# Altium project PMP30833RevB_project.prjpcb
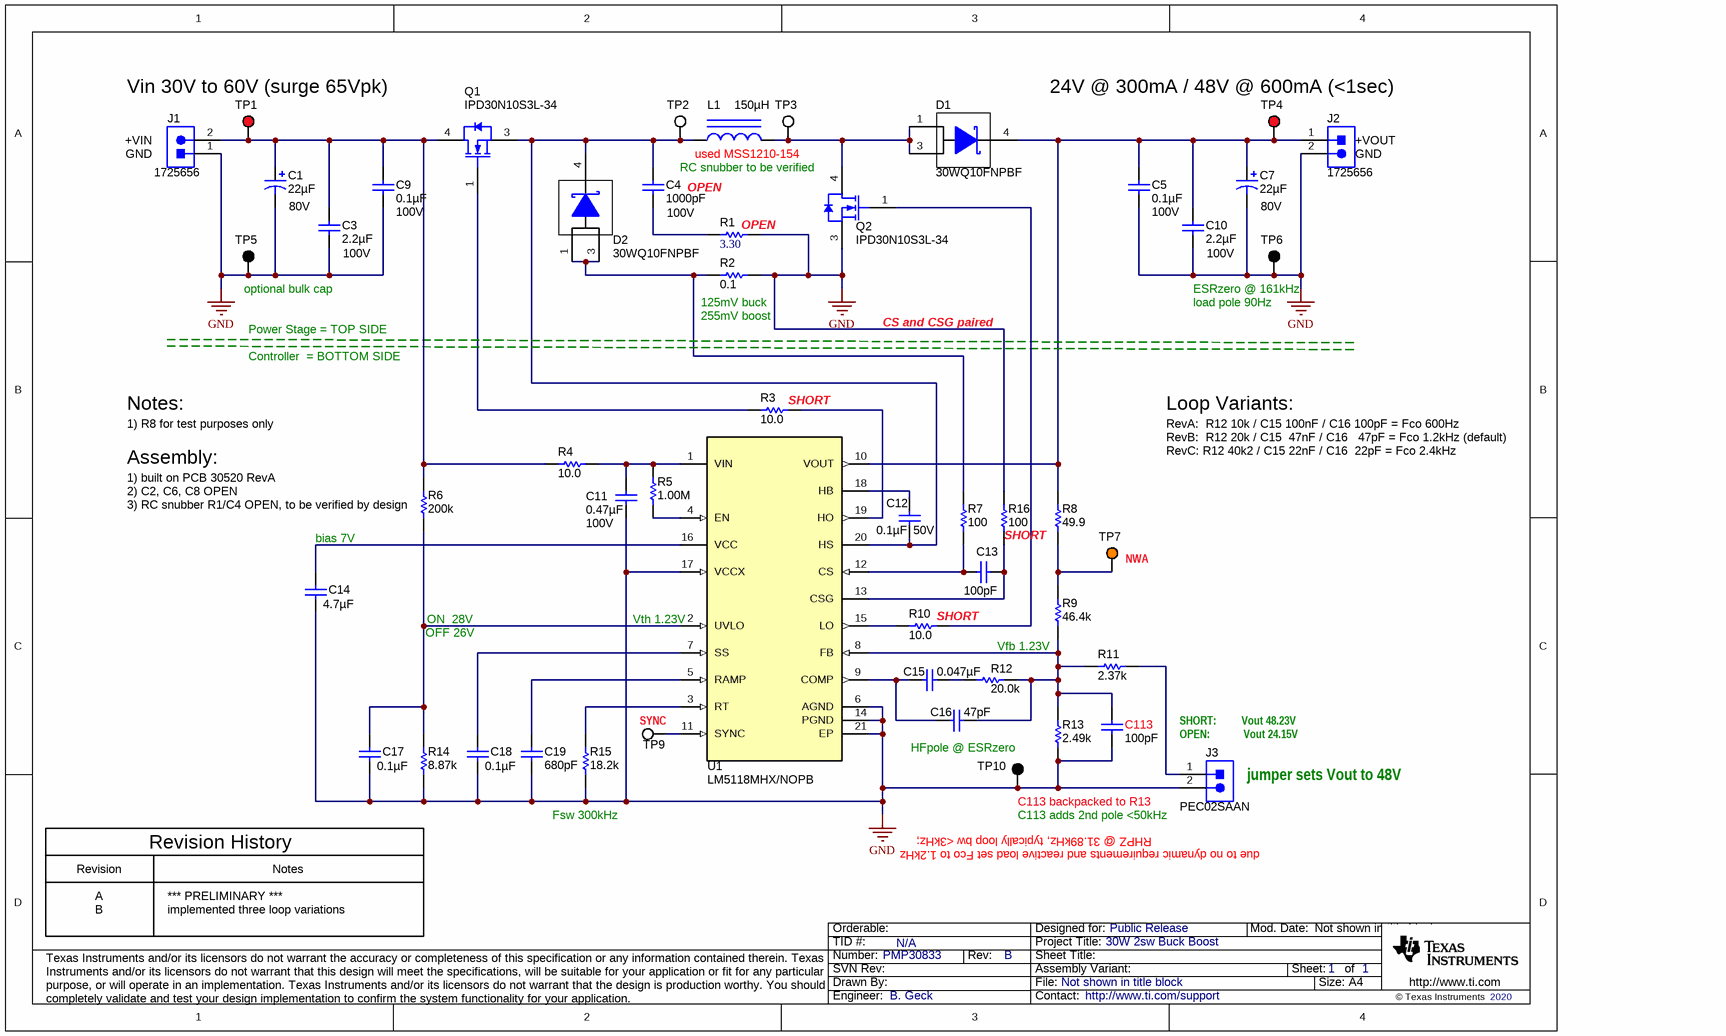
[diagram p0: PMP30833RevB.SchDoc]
CopyrightYear: 2020; PCB_Layout: B. Geck; PCB_Rev: A; PRJ_Customer: Public Release; PRJ_Engineer: B. Geck; PRJ_Number: PMP30833; PRJ_Title: 30W 2sw Buck Boost; SCH_Rev: B; TechSupport: http://www.ti.com/support; TID: N/A
1 sheet, 51 parts. Net scope: global (net labels, ports and power ports of the same name join across sheets).
Board file: PMP30520RevA_board.PcbDoc

## Sheet PMP30833RevB.SchDoc
size A4; Date: Not shown in title block; ApprovedBy: Not shown in title block; CheckedBy: Not shown in title block; Author: Not shown in title block; CompanyName: Not shown in title block; Engineer: Not shown in title block; Organization: Not shown in title block; Address1: Not shown in title block; Address2: Not shown in title block; Address3: Not shown in title block; Address4: Not shown in title block; DocumentNumber: 1; Revision: Use project parameter SCH_Rev; SheetNumber: 1; SheetTotal: 1; PageSetup: Record=PageOptions¦CenterHorizontal=True¦CenterVertical=True¦PrintScale=0.94¦XCorrection=1.00¦YCorrection=1.00¦PrintKind=0¦BorderSize=5000000¦LeftOffset=0¦BottomOffset=0¦Orientation=2¦PaperLength=1000¦PaperWidth=1000¦Scale=100¦PaperSource=15¦PrintQuality=600¦MediaType=1¦DitherType=10¦PrintScaleMode=1¦PaperKind=Letter

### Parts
C1  ValueDisplayed: 22µF  Value2: 80V  [SM_RADIAL_8MM]  (hidden comment: EEHZC1K220P)
C3  ValueDisplayed: 2.2µF  Value2: 100V  [1210_270]  (hidden comment: GRM32ER72A225KA35L)
C4  ValueDisplayed: 1000pF  Value2: 100V  [0603]  (hidden comment: GRM188R72A102KA01D)
C5  ValueDisplayed: 0.1µF  Value2: 100V  [0603]  (hidden comment: GRM188R72A104KA35D)
C7  ValueDisplayed: 22µF  Value2: 80V  [SM_RADIAL_8MM]  (hidden comment: EEHZC1K220P)
C9  ValueDisplayed: 0.1µF  Value2: 100V  [0603]  (hidden comment: GRM188R72A104KA35D)
C10  ValueDisplayed: 2.2µF  Value2: 100V  [1210_270]  (hidden comment: GRM32ER72A225KA35L)
C11  ValueDisplayed: 0.47µF  Value2: 100V  [0805_HV]  (hidden comment: GRM21BR72A474KA73L)
C12  ValueDisplayed: 0.1µF  Value2: 50V  [0603]  (hidden comment: GCM188R71H104KA57D)
C13  ValueDisplayed: 100pF  [0603]  (hidden comment: GRM1885C1H101JA01D)
C14  ValueDisplayed: 4.7µF  [0603]  (hidden comment: GRM188Z71C475KE21D)
C15  ValueDisplayed: 0.047µF  [0603]  (hidden comment: GRM188R71E473KA01D)
C16  ValueDisplayed: 47pF  [0603]  (hidden comment: GRM1885C1H470JA01D)
C17  ValueDisplayed: 0.1µF  [0603]  (hidden comment: GRM188R71E104KA01D)
C18  ValueDisplayed: 0.1µF  [0603]  (hidden comment: GRM188R71E104KA01D)
C19  ValueDisplayed: 680pF  [0603]  (hidden comment: GRM1885C1E681JA01D)
C113  ValueDisplayed: 100pF  [0603]  (hidden comment: GRM1885C1H101JA01D)
D1  30WQ10FNPBF  [DPAK]
D2  30WQ10FNPBF  [DPAK]
J1  1725656  [CONN_1725656]
J2  1725656  [CONN_1725656]
J3  PEC02SAAN  [CONN_PEC02SAAN]
L1  ValueDisplayed: 150µH  [MSS1210]  (hidden comment: MSS1210-154KE)
Q1  IPD30N10S3L-34  [DPAK]
Q2  IPD30N10S3L-34  [DPAK]
R1  ValueDisplayed: 3.30  [1210M]  (hidden comment: CRCW12103R30FKEAHP)
R2  ValueDisplayed: 0.1  [1206]  (hidden comment: ERJ-8BWFR100V)
R3  ValueDisplayed: 10.0  [0603]  (hidden comment: CRCW060310R0FKEA)
R4  ValueDisplayed: 10.0  [0603]  (hidden comment: CRCW060310R0FKEA)
R5  ValueDisplayed: 1.00M  [0603]  (hidden comment: CRCW06031M00FKEA)
R6  ValueDisplayed: 200k  [0603]  (hidden comment: CRCW0603200KFKEA)
R7  ValueDisplayed: 100  [0603]  (hidden comment: CRCW0603100RFKEA)
R8  ValueDisplayed: 49.9  [0603]  (hidden comment: CRCW060349R9FKEA)
R9  ValueDisplayed: 46.4k  [0603]  (hidden comment: CRCW060346K4FKEA)
R10  ValueDisplayed: 10.0  [0603]  (hidden comment: CRCW060310R0FKEA)
R11  ValueDisplayed: 2.37k  [0603]  (hidden comment: CRCW06032K37FKEA)
R12  ValueDisplayed: 20.0k  [0603]  (hidden comment: CRCW060320K0FKEA)
R13  ValueDisplayed: 2.49k  [0603]  (hidden comment: CRCW06032K49FKEA)
R14  ValueDisplayed: 8.87k  [0603]  (hidden comment: CRCW06038K87FKEA)
R15  ValueDisplayed: 18.2k  [0603]  (hidden comment: CRCW060318K2FKEA)
R16  ValueDisplayed: 100  [0603]  (hidden comment: CRCW0603100RFKEA)
TP1  5000  [Keystone5000]  (value not drawn)
TP2  5002  [Keystone5002]  (value not drawn)
TP3  5002  [Keystone5002]  (value not drawn)
TP4  5000  [Keystone5000]  (value not drawn)
TP5  5001  [Keystone5001]  (value not drawn)
TP6  5001  [Keystone5001]  (value not drawn)
TP7  5003  [Keystone5003]  (value not drawn)
TP9  5002  [Keystone5002]  (value not drawn)
TP10  5001  [Keystone5001]  (value not drawn)
U1  LM5118MHX/NOPB  [PWP0020A_N]

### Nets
GND: C1.2(-) C3.2 C5.2 C7.2(-) C9.2 C10.2 C11.2 C14.2 C17.2 C18.2 C19.2 C113.2 J1.1 J2.2 J3.2 Q2.3(S) R1.1 R2.2 R13.1 R14.1 R15.1 R16.2 TP5.1 TP6.1 TP10.1 U1.6(AGND) U1.14(PGND) U1.17(VCCX) U1.21(EP)
NetC1_1: C1.1(+) C3.1 C9.1 J1.2 Q1.4(D) R4.2 R6.2 TP1.1
NetC4_1: C4.1 C12.1 D2.4(K) L1.1 Q1.3(S) TP2.1 U1.20(HS)
NetC4_2: C4.2 R1.2
NetC5_1: C5.1 C7.1(+) C10.1 D1.4(K) J2.1 R8.2 TP4.1 U1.10(VOUT)
NetC11_1: C11.1 R4.1 R5.2 U1.1(VIN)
NetC12_2: C12.2 U1.18(HB)
NetC13_1: C13.1 R16.1 U1.13(CSG)
NetC13_2: C13.2 R7.1 U1.12(CS)
NetC14_1: C14.1 U1.16(VCC)
NetC15_1: C15.1 R12.1
NetC15_2: C15.2 C16.2 U1.9(COMP)
NetC16_1: C16.1 C113.1 R9.1 R11.2 R12.2 R13.2 U1.8(FB)
NetC17_1: C17.1 R6.1 R14.2 U1.2(UVLO)
NetC18_1: C18.1 U1.7(SS)
NetC19_1: C19.1 U1.5(RAMP)
NetD1_1: D1.1(A) D1.3(A) L1.2 Q2.4(D) TP3.1
NetD2_1: D2.1(A) D2.3(A) R2.1 R7.2
NetJ3_1: J3.1 R11.1
NetQ1_1: Q1.1(G) R3.2
NetQ2_1: Q2.1(G) R10.1
NetR3_1: R3.1 U1.19(HO)
NetR5_1: R5.1 U1.4(EN)
NetR8_1: R8.1 R9.2 TP7.1
NetR10_2: R10.2 U1.15(LO)
NetR15_2: R15.2 U1.3(RT)
NetTP9_1: TP9.1 U1.11(SYNC)

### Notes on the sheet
- Vin 30V to 60V (surge 65Vpk)
- 24V @ 300mA / 48V @ 600mA (<1sec)
- (near J1) +VIN
- (near J1) GND
- (near L1) used MSS1210-154
- RC snubber to be verified
- (near J2) +VOUT
- (near J2) GND
- OPEN
- (near R1) OPEN
- (near TP5) optional bulk cap
- (near R2) 125mV buck
- (near R2) 255mV boost
- (near TP6) ESRzero @ 161kHz
- (near TP6) load pole 90Hz
- Power Stage = TOP SIDE
- Controller  = BOTTOM SIDE
- CS and CSG paired
- Notes:
- 1) R8 for test purposes only
- (near R3) SHORT
- Loop Variants:
- RevA:  R12 10k / C15 100nF / C16 100pF = Fco 600Hz
- RevB:  R12 20k / C15  47nF / C16   47pF = Fco 1.2kHz (default)
- RevC: R12 40k2 / C15 22nF / C16  22pF = Fco 2.4kHz
- 1) built on PCB 30520 RevA
- Assembly:
- 2) C2, C6, C8 OPEN
- (near R6) 3) RC snubber R1/C4 OPEN, to be verified by design
- (near C14) bias 7V
- (near R16) SHORT
- (near TP7) NWA
- ON  28V
- OFF 26V
- (near U1) Vth 1.23V
- (near R10) SHORT
- (near R9) Vfb 1.23V
- (near TP9) SYNC
- SHORT:         Vout 48.23V
- HFpole @ ESRzero
- (near J3) OPEN:            Vout 24.15V
- (near J3) jumper sets Vout to 48V
- Revision History
- Fsw 300kHz
- (near TP10) C113 backpacked to R13
- C113 adds 2nd pole <50kHz
- RHPZ @ 31.89kHz, typically loop bw <3kHz;
- due to no dynamic requirements and reactive load set Fco to 1.2kHz
- Revision
- A
- B
- *** PRELIMINARY ***
- implemented three loop variations
- Notes

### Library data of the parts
C1 C7 = EEHZC1J330P: CAP, Polymer Hybrid, 22 µF, 80 V,+/- 20%, 45 mohm, 8x10 SMD; Manufacturer: Panasonic; Polarized: Y; CompType: Capacitor; Value: 22uF; U/M: EA; Cap_F: 0.000022; Tolerance_%: 20; Value1: 45 mohm; VDC_V: 80; ESR_ohm: 45; IRMS_A: 1.05; TaMin_C: -55; TaMax_C: 125; SizeAreaWB_mm2: 113.3; SizeArea_mm2: 74.7; SizeX_mm: 9; SizeY_mm: 8.3; SizeZ_mm: 10.2; AEC Category: Q200
C3 C10 = GRM32ER72A225KA35L: CAP, CERM, 2.2 µF, 100 V,+/- 10%, X7R, 1210; Manufacturer: MuRata; Polarized: N; CompType: Capacitor; Value: 2.2uF; U/M: EA; Cap_F: 0.0000022; Tolerance_%: 10; ESR_ohm: 0.007; Value1: 0.007 ohm; VDC_V: 100; IRMS_A: 4.4; TaMin_C: -55; TaMax_C: 125; Cap_Case: 1210; SizeArea_mm2: 8; SizeAreaWB_mm2: 14.7; SizeX_mm: 3.2; SizeY_mm: 2.5; SizeZ_mm: 2.7; AEC Category: Q200; Green_Lifecycle: Active; Green_REACh: Passed
C4 = GRM188R72A102KA01D: CAP, CERM, 1000 pF, 100 V,+/- 10%, X7R, 0603; Manufacturer: MuRata; Polarized: N; CompType: Capacitor; Value: 1000pF; U/M: EA; Cap_F: 0.000000001; Tolerance_%: 10; VDC_V: 100; TaMin_C: -55; TaMax_C: 125; SizeArea_mm2: 1.28; SizeAreaWB_mm2: 4.68; SizeX_mm: 1.6; SizeY_mm: 0.8; SizeZ_mm: 1; AEC Category: Q200; Green_Lifecycle: Active; Green_REACh: Passed
C5 C9 = GRM188R72A104KA35D: CAP, CERM, 0.1 µF, 100 V,+/- 10%, X7R, 0603; Manufacturer: MuRata; Polarized: N; CompType: Capacitor; Value: 0.1uF; U/M: EA; Cap_F: 0.0000001; Tolerance_%: 10; VDC_V: 100; TaMin_C: -55; TaMax_C: 125; SizeArea_mm2: 1.28; SizeAreaWB_mm2: 4.68; SizeX_mm: 1.6; SizeY_mm: 0.8; SizeZ_mm: 1; AEC Category: Q200; Green_Lifecycle: Active; Green_REACh: Passed
C11 = GRM21BR72A474KA73L: CAP, CERM, 0.47 µF, 100 V,+/- 10%, X7R, 0805; Manufacturer: MuRata; Polarized: N; CompType: Capacitor; Value: 0.47uF; U/M: EA; Cap_F: 0.00000047; Tolerance_%: 10; VDC_V: 100; TaMin_C: -55; TaMax_C: 125; Cap_Case: 0805; SizeArea_mm2: 2.5; SizeAreaWB_mm2: 6.75; SizeX_mm: 2; SizeY_mm: 1.25; SizeZ_mm: 1.45; AEC Category: Q200; Green_Lifecycle: Active; Green_REACh: Passed
C12 = GCM188R71H104KA57D: CAP, CERM, 0.1 µF, 50 V,+/- 10%, X7R, 0603; Manufacturer: MuRata; Polarized: N; CompType: Capacitor; Value: 0.1uF; U/M: EA; Cap_F: 0.0000001; Tolerance_%: 10; ESR_ohm: 0.02; Value1: 0.02 ohm; VDC_V: 50; IRMS_A: 1.84; TaMin_C: -55; TaMax_C: 125; SizeArea_mm2: 1.28; SizeAreaWB_mm2: 4.68; SizeX_mm: 1.6; SizeY_mm: 0.8; SizeZ_mm: 1; AEC Category: Q200; Green_Lifecycle: Active; Green_REACh: Passed
C13 C113 = GRM1885C1H101JA01D: CAP, CERM, 100 pF, 50 V,+/- 5%, C0G/NP0, 0603; Manufacturer: MuRata; Polarized: N; CompType: Capacitor; Value: 100pF; U/M: EA; Cap_F: 0.0000000001; Tolerance_%: 5; VDC_V: 50; Value2: 50V; TaMin_C: -55; TaMax_C: 125; SizeArea_mm2: 1.28; SizeAreaWB_mm2: 4.68; SizeX_mm: 1.6; SizeY_mm: 0.8; SizeZ_mm: 1; AEC Category: Q200; Green_Lifecycle: Active; Green_REACh: Passed
C14 = GRM188Z71C475KE21D: CAP, CERM, 4.7 µF, 16 V,+/- 10%, X7R, 0603; Manufacturer: MuRata; Polarized: N; CompType: Capacitor; Value: 4.7uF; U/M: EA; Cap_F: 0.0000047; Tolerance_%: 10; VDC_V: 16; Value2: 16V; TaMin_C: -55; TaMax_C: 125; SizeArea_mm2: 1.28; SizeAreaWB_mm2: 4.68; SizeX_mm: 1.6; SizeY_mm: 0.8; SizeZ_mm: 1; AEC Category: Q200
C15 = GRM188R71E473KA01D: CAP, CERM, 0.047 µF, 25 V,+/- 10%, X7R, 0603; Manufacturer: MuRata; Polarized: N; CompType: Capacitor; Value: 0.047uF; U/M: EA; Cap_F: 0.000000047; Tolerance_%: 10; VDC_V: 25; Value2: 25V; TaMin_C: -55; TaMax_C: 125; SizeArea_mm2: 1.28; SizeAreaWB_mm2: 4.68; SizeX_mm: 1.6; SizeY_mm: 0.8; SizeZ_mm: 1; AEC Category: Q200; Green_Lifecycle: Active; Green_REACh: Passed
C16 = GRM1885C1H470JA01D: CAP, CERM, 47 pF, 50 V,+/- 5%, C0G/NP0, 0603; Manufacturer: MuRata; Polarized: N; CompType: Capacitor; Value: 47pF; U/M: EA; Cap_F: 0.000000000047; Tolerance_%: 5; VDC_V: 50; Value2: 50V; TaMin_C: -55; TaMax_C: 125; SizeArea_mm2: 1.28; SizeAreaWB_mm2: 4.68; SizeX_mm: 1.6; SizeY_mm: 0.8; SizeZ_mm: 1; AEC Category: Q200; Green_Lifecycle: Active; Green_REACh: Passed
C17 C18 = GRM188R71E104KA01D: CAP, CERM, 0.1 µF, 25 V,+/- 10%, X7R, 0603; Manufacturer: MuRata; Polarized: N; CompType: Capacitor; Value: 0.1uF; U/M: EA; Cap_F: 0.0000001; Tolerance_%: 10; VDC_V: 25; Value2: 25V; TaMin_C: -55; TaMax_C: 125; SizeArea_mm2: 1.28; SizeAreaWB_mm2: 4.68; SizeX_mm: 1.6; SizeY_mm: 0.8; SizeZ_mm: 1; AEC Category: Q200; Green_Lifecycle: Active; Green_REACh: Passed
C19 = GRM1885C1E681JA01D: CAP, CERM, 680 pF, 25 V,+/- 5%, C0G/NP0, 0603; Manufacturer: MuRata; Polarized: N; CompType: Capacitor; Value: 680pF; U/M: EA; Cap_F: 0.00000000068; Tolerance_%: 5; VDC_V: 25; Value2: 25V; TaMin_C: -55; TaMax_C: 125; SizeArea_mm2: 1.28; SizeAreaWB_mm2: 4.68; SizeX_mm: 1.6; SizeY_mm: 0.8; SizeZ_mm: 1; AEC Category: Q200
D1 D2 = 30WQ10FNPBF: Diode, Schottky, 100 V, 3.5 A, DPAK; Manufacturer: Vishay-Semiconductor; U/M: EA; Vf_V: 0.81; Value: 100V; Value1: 3.5A; Value2: 0.81V; Io_A: 3.5; Vr_V: 100; TJmax_C: 150; RJC_CperW: 4.7; SizeAreaWB_mm2: 101.7114; SizeArea_mm2: 64.8114; SizeX_mm: 9.91; SizeY_mm: 6.54; SizeZ_mm: 2.29; AEC Category: Q101; Green_Lifecycle: Not Set; Green_REACh: Incomplete
J1 J2 = 1725656: Terminal Block, 100mil, 2x1, 6A, 63V, TH; Manufacturer: Phoenix Contact; SymbolCreator: a0412235
J3 = PEC02SAAN: Header, 100mil, 2x1, Tin, TH; Manufacturer: Sullins Connector Solutions; SymbolCreator: a0412235; Pitch_mm: 2.54; Gender: Male; Shrouded: N; Row_Count: 1; Current_A: 3; Voltage_V: 1800; Cert_UL: Y; Green_Lifecycle: Not Set; Green_REACh: Incomplete
L1 = MSS1210-154KE: Inductor, Shielded, Ferrite, 150 µH, 2.5 A, 0.176 ohm, SMD; Manufacturer: Coilcraft; Value: 150uH; Ind_H: 150.0E-6; Imax_A: 2.5; Irms: 2.5A @ 40C rise; Isat: 3.4A @ 30% inductance drop; DCR_ohm: 0.176; Value2: 2.5A; SizeAreaWB_mm2: 204.49; SizeArea_mm2: 151.29; SizeX_mm: 12.3; SizeZ_mm: 10; AEC Category: Q200; Green_Lifecycle: Not Set; Green_REACh: Incomplete
Q1 Q2 = IPD90N04S304ATMA1: MOSFET, N-CH, 100 V, 30 A, AEC-Q101, DPAK; Manufacturer: Infineon Technologies; Alternate Manufacturer: None; U/M: EA; ChType: N; Value: 100V; VdsMax_V: 100; Value1: 0.031 ohm; Value2: 24 nC; QgTyp_nC: 24; Vgs_V: 20; IdsMax_A: 30; SizeAreaWB_mm2: 101.7114; SizeArea_mm2: 64.8114; SizeX_mm: 9.91; SizeY_mm: 6.54; SizeZ_mm: 2.29; AEC Category: Q101; AEC Qualified: Y; Green_Lifecycle: Not Set; Green_REACh: Incomplete
R1 = CRCW12103R30FKEAHP: RES, 3.30, 1%, 0.75 W, AEC-Q200 Grade 0, 1210; Manufacturer: Vishay-Dale; CompType: Resistor; Value: 3.30; Res_ohm: 3.3; Value_Code: 3R30; Tolerance_%: 1; Power_W: 0.75; Value2: 0.75W; TempCo: 100 ppm/C; SizeArea_mm2: 8; SizeAreaWB_mm2: 14.7; SizeX_mm: 3.2; SizeY_mm: 2.5; SizeZ_mm: 1.35; U/M: EA; AEC Category: Q200; AEC Qualified: Y; AEC Grade: 0
R2 = ERJ-8BWFR100V: RES, 0.1, 1%, 0.5 W, 1206; Manufacturer: Panasonic; CompType: Resistor; Value: 0.1; Value_Code: R100; Tolerance_%: 1; Power_W: 0.5; Value2: 0.5W; VDC_V: 0; TempCo: 150 ppm/C; SizeArea_mm2: 5.12; SizeX_mm: 3.2; SizeY_mm: 1.6; SizeZ_mm: 1.35; EIA_Code: E96; U/M: EA; AEC Category: Q200
R3 R4 R10 = CRCW060310R0FKEA: RES, 10.0, 1%, 0.1 W, 0603; Manufacturer: Vishay-Dale; CompType: Resistor; Value: 10.0; Res_ohm: 10; Value_Code: 10R0; Tolerance_%: 1; Power_W: 0.1; Value2: 0.1W; VDC_V: 75; TempCo: 100 ppm/C; SizeArea_mm2: 1.28; SizeX_mm: 1.6; SizeY_mm: 0.8; EIA_Code: E96; U/M: EA; AEC Category: Q200; Green_Lifecycle: Active; Green_REACh: Passed
R5 = CRCW06031M00FKEA: RES, 1.00 M, 1%, 0.1 W, 0603; Manufacturer: Vishay-Dale; CompType: Resistor; Value: 1.00Meg; Res_ohm: 1000000; Value_Code: 1M00; Tolerance_%: 1; Power_W: 0.1; Value2: 0.1W; VDC_V: 75; TempCo: 100 ppm/C; SizeArea_mm2: 1.28; SizeX_mm: 1.6; SizeY_mm: 0.8; EIA_Code: E96; U/M: EA; AEC Category: Q200; Green_Lifecycle: Active; Green_REACh: Passed
R6 = CRCW0603200KFKEA: RES, 200 k, 1%, 0.1 W, 0603; Manufacturer: Vishay-Dale; CompType: Resistor; Value: 200k; Res_ohm: 200000; Tolerance_%: 1; Power_W: 0.1; Value2: 0.1W; VDC_V: 75; TempCo: 100 ppm/C; SizeArea_mm2: 1.28; SizeX_mm: 1.6; SizeY_mm: 0.8; EIA_Code: E96; U/M: EA; AEC Category: Q200; Green_Lifecycle: Active; Green_REACh: Passed
R7 R16 = CRCW0603100RFKEA: RES, 100, 1%, 0.1 W, 0603; Manufacturer: Vishay-Dale; CompType: Resistor; Value: 100; Value_Code: 100R; Tolerance_%: 1; Power_W: 0.1; Value2: 0.1W; VDC_V: 75; TempCo: 100 ppm/C; SizeArea_mm2: 1.28; SizeX_mm: 1.6; SizeY_mm: 0.8; EIA_Code: E96; U/M: EA; AEC Category: Q200; Green_Lifecycle: Active; Green_REACh: Passed
R8 = CRCW060349R9FKEA: RES, 49.9, 1%, 0.1 W, 0603; Manufacturer: Vishay-Dale; CompType: Resistor; Value: 49.9; Value_Code: 49R9; Tolerance_%: 1; Power_W: 0.1; Value2: 0.1W; VDC_V: 75; TempCo: 100 ppm/C; SizeArea_mm2: 1.28; SizeX_mm: 1.6; SizeY_mm: 0.8; EIA_Code: E96; U/M: EA; AEC Category: Q200; Green_Lifecycle: Active; Green_REACh: Passed
R9 = CRCW060346K4FKEA: RES, 46.4 k, 1%, 0.1 W, 0603; Manufacturer: Vishay-Dale; CompType: Resistor; Value: 46.4k; Res_ohm: 46400; Value_Code: 46k4; Tolerance_%: 1; Power_W: 0.1; Value2: 0.1W; VDC_V: 75; TempCo: 100 ppm/C; SizeArea_mm2: 1.28; SizeX_mm: 1.6; SizeY_mm: 0.8; EIA_Code: E96; U/M: EA; AEC Category: Q200; Green_Lifecycle: Active; Green_REACh: Passed
R11 = CRCW06032K37FKEA: RES, 2.37 k, 1%, 0.1 W, 0603; Manufacturer: Vishay-Dale; CompType: Resistor; Value: 2.37k; Res_ohm: 2370; Value_Code: 2k37; Tolerance_%: 1; Power_W: 0.1; Value2: 0.1W; VDC_V: 75; TempCo: 100 ppm/C; SizeArea_mm2: 1.28; SizeX_mm: 1.6; SizeY_mm: 0.8; EIA_Code: E96; U/M: EA; AEC Category: Q200
R12 = CRCW060320K0FKEA: RES, 20.0 k, 1%, 0.1 W, 0603; Manufacturer: Vishay-Dale; CompType: Resistor; Value: 20.0k; Res_ohm: 20000; Value_Code: 20k0; Tolerance_%: 1; Power_W: 0.1; Value2: 0.1W; VDC_V: 75; TempCo: 100 ppm/C; SizeArea_mm2: 1.28; SizeX_mm: 1.6; SizeY_mm: 0.8; EIA_Code: E96; U/M: EA; AEC Category: Q200; Green_Lifecycle: Active; Green_REACh: Passed
R13 = CRCW06032K49FKEA: RES, 2.49 k, 1%, 0.1 W, 0603; Manufacturer: Vishay-Dale; CompType: Resistor; Value: 2.49k; Res_ohm: 2490; Value_Code: 2k49; Tolerance_%: 1; Power_W: 0.1; Value2: 0.1W; VDC_V: 75; TempCo: 100 ppm/C; SizeArea_mm2: 1.28; SizeX_mm: 1.6; SizeY_mm: 0.8; EIA_Code: E96; U/M: EA; AEC Category: Q200; Green_Lifecycle: Active; Green_REACh: Passed
R14 = CRCW06038K87FKEA: RES, 8.87 k, 1%, 0.1 W, 0603; Manufacturer: Vishay-Dale; CompType: Resistor; Value: 8.87k; Res_ohm: 8870; Value_Code: 8k87; Tolerance_%: 1; Power_W: 0.1; Value2: 0.1W; VDC_V: 75; TempCo: 100 ppm/C; SizeArea_mm2: 1.28; SizeX_mm: 1.6; SizeY_mm: 0.8; EIA_Code: E96; U/M: EA; AEC Category: Q200; Green_Lifecycle: Active; Green_REACh: Passed
R15 = CRCW060318K2FKEA: RES, 18.2 k, 1%, 0.1 W, 0603; Manufacturer: Vishay-Dale; CompType: Resistor; Value: 18.2k; Res_ohm: 18200; Value_Code: 18k2; Tolerance_%: 1; Power_W: 0.1; Value2: 0.1W; VDC_V: 75; TempCo: 100 ppm/C; SizeArea_mm2: 1.28; SizeX_mm: 1.6; SizeY_mm: 0.8; EIA_Code: E96; U/M: EA; AEC Category: Q200; Green_Lifecycle: Active; Green_REACh: Passed
TP1 TP4 = 5000: Test Point, Miniature, Red, TH; Manufacturer: Keystone; CompType: Test Point Loop; U/M: EA
TP2 TP3 TP9 = 5002: Test Point, Miniature, White, TH; Manufacturer: Keystone; CompType: Test Point Loop; ContactFinish: Silver
TP5 TP6 TP10 = 5001: Test Point, Miniature, Black, TH; Manufacturer: Keystone; CompType: Test Point Loop; U/M: EA
TP7 = 5003: Test Point, Miniature, Orange, TH; Manufacturer: Keystone; CompType: Test Point Loop; ContactFinish: Silver
U1 = LM25118Q1MHX/NOPB: 3-75V Wide Vin, Current Mode Non-Synchronous Buck-Boost Controller, PWP0020A (TSSOP-20); Alternate PartNumber: LM5118MH/NOPB; Manufacturer: Texas Instruments; SymbolCreator: Altium; SizeArea_mm2: 41.6; SizeAreaWB_mm2: 71.4; SizeX_mm: 6.4; SizeY_mm: 6.5; SizeZ_mm: 1.2; CompType: IC; U/M: EA

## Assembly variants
001: not fitted FID1 FID2 FID3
